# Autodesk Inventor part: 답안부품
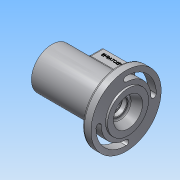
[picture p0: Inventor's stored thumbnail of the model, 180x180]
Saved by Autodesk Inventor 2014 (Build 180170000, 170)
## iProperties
Created: 2017-05
Part Number: 답안부품
Material: 알루미늄 6061
Document SubType Name: Modeling
Designer: NET
Density: 2.71 g/cm^3
Appearance: 알루미늄 - 평지
Mass: 734.189 g
Surface Area: 637.35 cm^2
Volume: 270.918 cm^3
Author: NET
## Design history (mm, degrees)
sketch "스케치1"
  geometry: L1 (-57.5, 31)-(57.5, 31); L2 (57.5, 31)-(57.5, 0); L3 (57.5, 0)-(-57.5, 0); L4 (-57.5, 0)-(-57.5, 31); 2 further points
  constraints: 8 end point, 2 coincident, 2 parallel, 1 horizontal, 1 midpoint, 1 perpendicular
  dimensions: "d0" = 62 diameter of L1.end L3; "d1" = 115 distance of L1.start L1.end
revolve "회전1" sketch "스케치1" stored, may be unused: angle "d2" = 90 deg
node "작업 평면1"
sketch "스케치2"
  geometry: C1 r 53 at (0, 0); 1 further point
  constraints: 1 centre point, 1 coincident
  dimensions: "d4" = 106 diameter of C1
extrude "돌출1" join sketch "스케치2" distance "d5" = 13; taper "d6" = 0 deg
fillet "모깎기1" dims "d7" = 3
sketch "스케치3"
  geometry: L1 (-57.5, -31)-(-57.5, 31) reference; L2 (-57.5, 31)-(41.5, 31) reference; L3 (41.5, 31)-(41.5, 50) reference; L4 (44.5, 53)-(54.5, 53) reference; L5 (54.5, 53)-(54.5, 31) reference; L6 (54.5, 31)-(57.5, 31) reference; L7 (57.5, 31)-(57.5, -31) reference; L8 (57.5, -31)-(54.5, -31) reference; L9 (54.5, -31)-(54.5, -53) reference; L10 (54.5, -53)-(44.5, -53) reference; L11 (41.5, -50)-(41.5, -31) reference; L12 (41.5, -31)-(-57.5, -31) reference; L13 (-57.5, 0)-(57.5, 0); L14 (57.5, 0)-(57.5, 22); L15 (57.5, 22)-(45.318, 16.779); L16 (43.5, 14.022)-(43.5, 12.904); L17 (42.8, 12.5)-(36.5, 12.5); L18 (36.2, 12.2)-(36.2, 10); L19 (36.2, 10)-(33.5, 10); L20 (33.5, 10)-(33.5, 13.5); L21 (30.5, 16.5)-(28.5, 16.5); L22 (28.5, 16.5)-(28.5, 17.2); L23 (28.2, 17.5)-(18.5, 17.5); L24 (17.5, 18.5)-(17.5, 23); L25 (43.5, 12.904)-(42.8, 12.5); L26 (14.5, 26)-(-17.5, 26); L27 (-20.5, 23)-(-20.5, 18.5); L28 (-21.5, 17.5)-(-31.5, 17.5); L29 (-31.5, 17.5)-(-31.5, 18.5); L30 (-31.5, 18.5)-(-33.25, 18.5); L31 (-33.25, 18.5)-(-33.25, 17.5); L32 (-33.25, 17.5)-(-38.25, 17.5); L33 (-38.25, 17.5)-(-38.25, 20); L34 (-38.25, 20)-(-44.25, 20); L35 (-44.25, 20)-(-44.25, 24); L36 (-44.25, 24)-(-47.25, 24); L37 (-47.25, 24)-(-47.25, 0); L38 (-21.5, 17.5)-(-20.5, 18.5); L39 (17.5, 18.5)-(18.5, 17.5); A1 r 3 centre (44.5, 50) between (44.5, 53) and (41.5, 50) reference; A2 r 3 centre (44.5, -50) between (41.5, -50) and (44.5, -53) reference; A3 r 0.3 centre (36.5, 12.2) between (36.5, 12.5) and (36.2, 12.2); A4 r 3 centre (30.5, 13.5) between (33.5, 13.5) and (30.5, 16.5); A5 r 3 centre (46.5, 14.022) between (45.318, 16.779) and (43.5, 14.022); A6 r 3 centre (14.5, 23) between (17.5, 23) and (14.5, 26); A7 r 3 centre (-17.5, 23) between (-17.5, 26) and (-20.5, 23); A8 r 0.3 centre (28.2, 17.2) between (28.5, 17.2) and (28.2, 17.5); 11 further points
  constraints: 54 end point, 18 point on line, 13 perpendicular, 12 point on circle, 12 tangent, 7 parallel, 6 centre point, 3 midpoint, 1 collinear, 1 vertical alignment
  dimensions: "d57" = 24 horizontal distance of L13.end point (33.5, 16.5); "d58" = 5 distance of point (33.5, 16.5) L21.end; "d62" = 44 diameter of L14.end L13; "d64" = 14 distance from line of L14.end L16; "d66" = 32 diameter of point (43.5, 16) L13; "d67" = 30 deg angle of L25 L17; "d68" = 0.7 horizontal distance of L16.end L17.start; "d69" = 7.3 horizontal distance of L16.end point (36.2, 12.5); "d70" = 0.3 radius of A3; "d71" = 25 diameter of L17 L13; "d72" = 20 diameter of L19 L13; "d73" = 33 diameter of L21 L13; "d75" = 3 radius of A4; "d76" = 3 radius of A5; "d77" = 11 distance of point (28.5, 17.5) point (17.5, 17.5); "d78" = 38 distance of point (17.5, 26) point (-20.5, 26); "d79" = 52 diameter of L26 L13; "d80" = 35 diameter of L23 L13; "d81" = 3 radius of A6; "d82" = 3 radius of A7; "d83" = 11 distance of point (-20.5, 17.5) L28.end; "d84" = 1.75 distance of L29.end L30.end; "d85" = 35 diameter of L28 L13; "d86" = 1 distance of L28.start point (-20.5, 17.5); "d87" = 1 distance of L27.end point (-20.5, 17.5) (= d86); "d88" = 1 distance of L24.start point (17.5, 17.5) (= d86); "d89" = 1 distance of L23.end point (17.5, 17.5) (= d88); "d90" = 37 diameter of L30 L13; "d91" = 3 distance of L35.end L36.end; "d92" = 9 horizontal distance of L36.end L33.end; "d94" = 48 diameter of L36 L13; "d95" = 40 diameter of L34 L13; "d96" = 35 diameter of L32 L13; "d97" = 0.3 radius of A8; "d152" = 5 distance of L31.end L32.end
revolve "회전2" sketch "스케치3" stored, may be unused: angle "d98" = 90 deg
sketch "스케치4"
  geometry: C1 r 31 at (0, 0) reference; 1 further point
  constraints: 1 coincident
hole "구멍1" sketch "스케치4" at (0, 0) diameter "d99" = 40.376; stored, may be unused: countersink angle "d103" = 90 deg, drill point angle "d105" = 0 deg; dims "d100" = 9, "d101" = 4, "d102" = 2, "d104" = 11
sketch "스케치5"
  geometry: C1 r 31 at (0, 0) reference; A1 r 41.5 centre (0, 0) between (41.5, 0) and (0, -41.5); A2 r 4 centre (41.5, 0) between (45.5, 0) and (37.5, 0); A3 r 4 centre (0, -41.5) between (0, -37.5) and (0, -45.5); A4 r 4 centre (0, 41.5) between (0, 37.5) and (0, 45.5); A5 r 4 centre (-41.5, 0) between (-45.5, 0) and (-37.5, 0); A6 r 45.5 centre (0, 0) between (0, 45.5) and (-45.5, 0); A7 r 45.5 centre (0, 0) between (0, -45.5) and (45.5, 0); A8 r 37.5 centre (0, 0) between (0, 37.5) and (-37.5, 0); A9 r 37.5 centre (0, 0) between (0, -37.5) and (37.5, 0)
  constraints: 20 point on circle, 9 centre point, 3 coincident
  dimensions: "d106" = 83 diameter of A1; "d109" = 8 diameter of A2; "d110" = 8 diameter of A3; "d111" = 8 diameter of A4; "d112" = 8 diameter of A5
extrude "돌출2" cut sketch "스케치5" stored distance "d113" = 14; taper "d114" = 0 deg
node "작업 평면2"
sketch "스케치6"
  geometry: L1 (-23.5, -20)-(-23.5, 20); L2 (-23.5, 20)-(26.5, 20); L3 (26.5, 20)-(26.5, -20); L4 (26.5, -20)-(-23.5, -20); L5 (1.5, -20)-(1.5, 20); L6 (-23.5, 0)-(26.5, 0); L7 (57.5, 31)-(57.5, -31) reference; 1 further point
  constraints: 12 end point, 4 midpoint, 2 parallel, 2 perpendicular, 1 horizontal alignment, 1 vertical
  dimensions: "d118" = 56 distance from line of L5.start L7; "d119" = 50 distance from line of L1 L6.end; "d120" = 40 distance between parallel lines of L2 L4
extrude "돌출3" join sketch "스케치6" stored distance "d121" = 14; taper "d122" = 0 deg
sketch "스케치7"
  geometry: L1 (-26.5, 20)-(23.5, 20) reference; L2 (-26.5, -20)-(-26.5, 20) reference; L3 (23.5, -20)-(-26.5, -20) reference; L4 (-1.5, 20)-(-1.5, -20); L5 (-17.5, 11)-(14.5, 11); L6 (14.5, 11)-(14.5, -11); L7 (14.5, -11)-(-17.5, -11); L8 (-17.5, -11)-(-17.5, 11); 4 further points
  constraints: 10 end point, 5 midpoint, 2 parallel, 1 horizontal, 1 horizontal alignment, 1 perpendicular, 1 vertical alignment
  dimensions: "d129" = 32 distance of L5.start L5.end; "d130" = 22 distance of L5.end L6.end
extrude "돌출4" cut sketch "스케치7" stored distance "d125" = 14; taper "d126" = 0 deg
fillet "모깎기2" dims "d127" = 3
fillet "모깎기3" dims "d128" = 3
sketch "스케치8"
  geometry: L1 (-17.5, 11)-(14.5, 11) reference; L2 (14.5, -11)-(-17.5, -11) reference; L3 (-1.5, 11)-(-1.5, -11); L4 (-22, 15.5)-(19, 15.5); L5 (19, 15.5)-(19, -15.5); L6 (19, -15.5)-(-22, -15.5); L7 (-22, -15.5)-(-22, 15.5); 9 further points
  constraints: 10 end point, 6 midpoint, 4 coincident, 2 parallel, 1 horizontal, 1 horizontal alignment, 1 perpendicular, 1 vertical alignment
  dimensions: "d132" = 41 distance of L4.start L4.end; "d133" = 31 distance of L4.end L5.end
hole "구멍2" sketch "스케치8" at (-22, 15.5), (19, 15.5), (-22, -15.5), (19, -15.5) diameter "d134" = 2.459; stored, may be unused: countersink angle "d138" = 90 deg, drill point angle "d140" = 118 deg; dims "d135" = 6, "d136" = 4, "d137" = 2, "d139" = 8
fillet "모깎기4" dims "d141" = 3
chamfer "모따기1" distance "d142" = 1; stored, may be unused: second distance "d143" = 2, angle "d144" = 45 deg
sketch "스케치9"
  geometry: L1 (44, 0)-(0, 0) reference; L2 (-34, -75)-(-34, -13) reference; 2 further points
  constraints: 1 other
  dimensions: "d145" = 56 distance from line of point (22, -8) L2; "d146" = 8 distance from line of L1 point (22, -8)
feature "엠보싱1" sketch "스케치9" dims "d147" = 0.5, "d148" = 0
chamfer "모따기2" distance "d149" = 1; stored, may be unused: second distance "d150" = 2, angle "d151" = 45 deg
node "솔리드1"
node "절단 모서리 투영1"
other parameters: "d3" = -3, "d107" = 75, "d108" = 91, "d115" = 44
